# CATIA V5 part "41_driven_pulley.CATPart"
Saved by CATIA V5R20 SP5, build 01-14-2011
Part number: 41_driven_pulley
Bounding box of the stored display mesh (mm): x -25.996 to 25.996, y 114.366 to 166.358, z -174.5 to -155.5
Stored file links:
  C:\Documents and Settings\anizard\Bureau\13\41_driven_pulley.CATPart
  C:\Documents and Settings\anizard\Bureau\13\anizard.CATProduct
  C:\Documents and Settings\anizard\Bureau\13\16_C-shaped_bracket.CATPart
  D:\Documents\T\2011-2012\CFAO\ThinkMotion\7\SqueletteV.CATPart
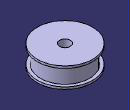
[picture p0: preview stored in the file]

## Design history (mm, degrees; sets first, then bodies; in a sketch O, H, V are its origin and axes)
Set1
  Line1: linked copy from another document
  Plane1: linked copy from another document
  Point1: linked copy from another document
  Plane2 to Plane4: linked copy from another document
  Point2: linked copy from another document
Body1 (main body)
  Sketch1 on yz-plane, origin (0, 0, 0), H (0, 1, 0), V (0, 0, 1)
    line L1 (145.3619, -155.5) -> (145.3619, -174.5)
    line L2 (145.3619, -174.5) -> (166.3619, -174.5)
    line L3 (166.3619, -174.5) -> (166.3619, -172.5)
    line L4 (166.3619, -172.5) -> (163.3619, -172.5)
    line L5 (163.3619, -172.5) -> (163.3619, -157.5)
    line L6 (163.3619, -157.5) -> (166.3619, -157.5)
    point P7 (166.3619, -157.5)
    line L7 (166.3619, -157.5) -> (166.3619, -155.5)
    line L8 (166.3619, -155.5) -> (145.3619, -155.5)
    reference projected point E1 (163.3619, -155.5) from Point1
    reference projected point E2 (145.3619, -155.5) from Point2
    reference intersected line E3 through (0, -174.5) direction (-1, 0) from Plane4
    reference intersected line E4 through (0, -172.5) direction (-1, 0) from Plane3
    reference intersected line E5 through (0, -157.5) direction (-1, 0) from Plane2
    reference intersected line E6 through (0, -155.5) direction (-1, 0) from Plane1
    distance L5 L3 = 3
    vertical: L1 V, L3 V, L5 V, L7 V
    horizontal: L2 H, L4 H, L6 H, L8 H
    coincidence: P7 L3, L5 E1, L1 E2, L2 E3, L4 E4, L6 E5, L8 E6
  Shaft1: profile Sketch1, axis Line1, angle 360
